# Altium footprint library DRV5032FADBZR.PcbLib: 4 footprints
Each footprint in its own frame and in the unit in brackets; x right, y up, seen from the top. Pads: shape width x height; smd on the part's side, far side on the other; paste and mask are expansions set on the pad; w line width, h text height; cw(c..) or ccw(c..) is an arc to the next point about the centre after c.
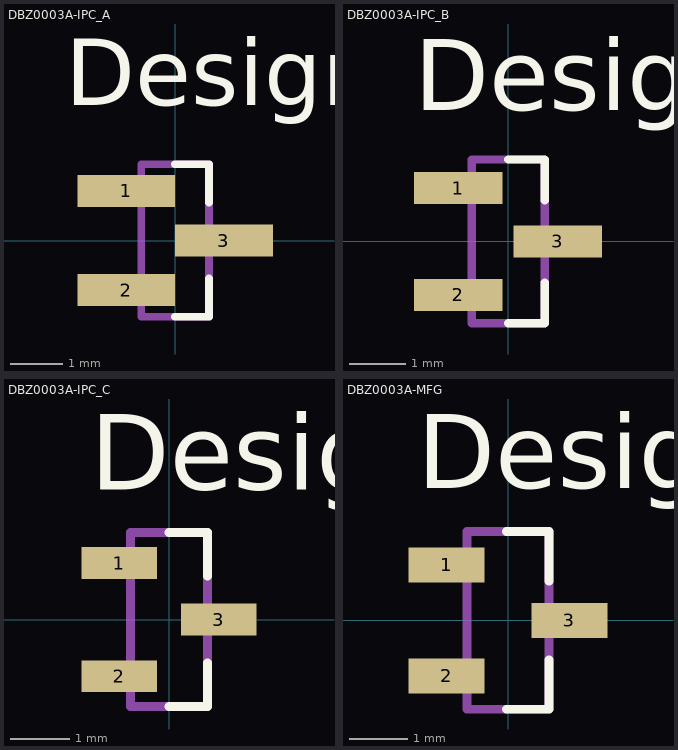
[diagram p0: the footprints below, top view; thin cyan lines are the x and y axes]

## DBZ0003A-IPC_A [mm]
pads (3):
  rect 1.874x0.612 smd paste+0 mask+0: 1(-0.935,0.95) 2(-0.935,-0.95) 3(0.935,0)
Top Overlay:
  lines w0.15: 0,-1.46 0.65,-1.46 0.65,-0.73 ; 0,1.46 0.65,1.46 0.65,0.73
  text "Designator577" at -2.108,2.591 h1.27
  text ".Designator" at -3.492,-0.635 h1.27
Mechanical 13:
  lines w0.15: -0.65,-1.46 -0.65,1.46 0.65,1.46 0.65,-1.46 -0.65,-1.46
  text ".Designator" at -3.492,-0.635 h1.27

## DBZ0003A-IPC_B [mm]
pads (3):
  rect 1.574x0.572 smd paste+0 mask+0: 1(-0.885,0.95) 2(-0.885,-0.95) 3(0.885,0)
Top Overlay:
  lines w0.15: 0,-1.46 0.65,-1.46 0.65,-0.73 ; 0,1.46 0.65,1.46 0.65,0.73
  text "Designator576" at -1.676,2.337 h1.27
  text ".Designator" at -3.492,-0.635 h1.27
Mechanical 13:
  lines w0.15: -0.65,-1.46 -0.65,1.46 0.65,1.46 0.65,-1.46 -0.65,-1.46
  text ".Designator" at -3.492,-0.635 h1.27

## DBZ0003A-IPC_C [mm]
pads (3):
  rect 1.274x0.532 smd paste+0 mask+0: 1(-0.835,0.95) 2(-0.835,-0.95) 3(0.835,0)
Top Overlay:
  lines w0.15: 0,-1.46 0.65,-1.46 0.65,-0.73 ; 0,1.46 0.65,1.46 0.65,0.73
  text "Designator575" at -1.321,2.184 h1.27
  text ".Designator" at -3.492,-0.635 h1.27
Mechanical 13:
  lines w0.15: -0.65,-1.46 -0.65,1.46 0.65,1.46 0.65,-1.46 -0.65,-1.46
  text ".Designator" at -3.492,-0.635 h1.27

## DBZ0003A-MFG [mm]
pads (3):
  rect 1.3x0.6 smd paste+0 mask+0: 1(-1.05,0.95) 2(-1.05,-0.95) 3(1.05,0)
Top Overlay:
  lines w0.15: -0.025,-1.52 0.7,-1.52 0.7,-0.675 ; -0.025,1.52 0.7,1.52 0.7,0.675
  text "Designator574" at -1.549,2.261 h1.27
  text ".Designator" at -3.492,-0.635 h1.27
Mechanical 13:
  lines w0.15: -0.7,-1.52 0.7,-1.52 0.7,1.52 -0.7,1.52 -0.7,-1.52
  text ".Designator" at -3.492,-0.635 h1.27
